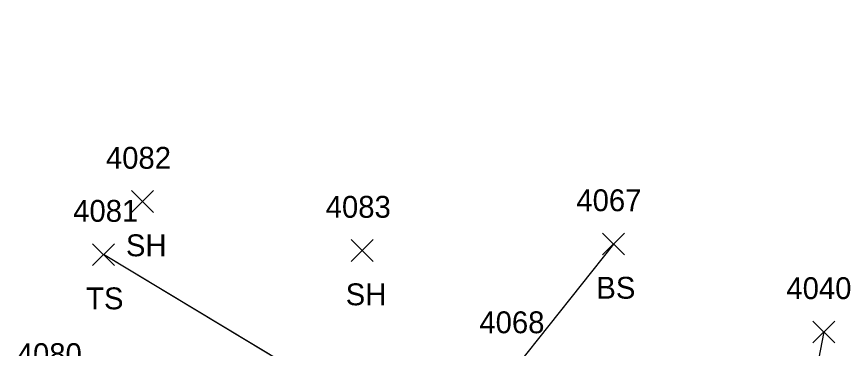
# Model space of a CAD drawing. Extents: x 1554668 to 1563881, y 831386 to 834374.
# Drawn here: x 1562190.3 to 1562266.5, y 834170.7 to 834201.1 of the extents above; entities that cross this region are included whole.
import ezdxf

# ---------------------------------------------------------------- set-up
doc = ezdxf.new("R2010")
doc.units = 0
for name, color, linetype in [('L_A', 7, 'Continuous'), ('L_I', 7, 'Continuous'), ('L_TIC', 7, 'Continuous'), ('LAWA', 7, 'Continuous'), ('LELB', 7, 'Continuous')]:
    doc.layers.add(name, color=color, linetype=linetype)

msp = doc.modelspace()

# ---------------------------------------------------------------- linework, layer by layer
at = {"layer": 'L_TIC'}
for points in [[(1562200.77, 834183.16), (1562202.77, 834185.16)], [(1562202.77, 834183.16), (1562200.77, 834185.16)], [(1562243.825, 834179.279), (1562245.825, 834181.279)], [(1562245.825, 834179.279), (1562243.825, 834181.279)], [(1562197.209, 834178.31), (1562199.209, 834180.31)], [(1562199.209, 834178.31), (1562197.209, 834180.31)], [(1562220.862, 834178.68), (1562222.862, 834180.68)], [(1562222.862, 834178.68), (1562220.862, 834180.68)], [(1562263.066, 834171.242), (1562265.066, 834173.242)], [(1562265.066, 834171.242), (1562263.066, 834173.242)]]:
    msp.add_lwpolyline(points, dxfattribs=at)
at = {"layer": 'LAWA'}
for points in [[(1562264.066, 834172.242), (1562260.28, 834152.616), (1562240.279, 834155.345), (1562220.249, 834159.389), (1562193.704, 834166.213), (1562151.516, 834189.235), (1562134.362, 834197.667), (1562108.95, 834212.49), (1562103.793, 834224.616), (1562105.925, 834242.465)], [(1562264.073, 834172.244), (1562260.287, 834152.618), (1562240.287, 834155.347), (1562220.256, 834159.393), (1562193.715, 834166.215), (1562151.519, 834189.239), (1562134.368, 834197.674), (1562108.954, 834212.498), (1562103.797, 834224.623), (1562105.929, 834242.473)], [(1562264.073, 834172.244), (1562260.287, 834152.618), (1562240.287, 834155.347), (1562220.256, 834159.393), (1562193.715, 834166.215), (1562151.519, 834189.239), (1562134.368, 834197.674), (1562108.954, 834212.498), (1562103.797, 834224.623), (1562105.929, 834242.473)], [(1562264.073, 834172.244), (1562260.287, 834152.618), (1562240.287, 834155.347), (1562220.256, 834159.393), (1562193.715, 834166.215), (1562151.519, 834189.239), (1562134.368, 834197.674), (1562108.954, 834212.498), (1562103.797, 834224.623), (1562105.929, 834242.473)]]:
    msp.add_lwpolyline(points, dxfattribs=at)
at = {"layer": 'LELB'}
for points in [[(1562244.825, 834180.279), (1562235.959, 834169.123), (1562225.766, 834162.716), (1562220.249, 834159.389)], [(1562244.833, 834180.281), (1562235.966, 834169.126), (1562225.775, 834162.717), (1562220.256, 834159.393)], [(1562244.833, 834180.281), (1562235.966, 834169.126), (1562225.775, 834162.717), (1562220.256, 834159.393)], [(1562244.833, 834180.281), (1562235.966, 834169.126), (1562225.775, 834162.717), (1562220.256, 834159.393)], [(1562238.678, 834156.759), (1562225.766, 834162.716), (1562198.209, 834179.31)], [(1562238.688, 834156.76), (1562225.775, 834162.717), (1562198.215, 834179.314)], [(1562238.688, 834156.76), (1562225.775, 834162.717), (1562198.215, 834179.314)], [(1562238.688, 834156.76), (1562225.775, 834162.717), (1562198.215, 834179.314)]]:
    msp.add_lwpolyline(points, dxfattribs=at)

# ---------------------------------------------------------------- texts
at = {"layer": 'L_A'}
for s, p in [('SH', (1562200.258, 834179.16)), ('BS', (1562243.266, 834175.279)), ('SH', (1562220.35, 834174.68)), ('TS', (1562196.618, 834174.31))]:
    msp.add_text(s, height=2, dxfattribs=at).set_placement(p)
at = {"layer": 'L_I'}
for s, p in [('4082', (1562198.431, 834187.16)), ('4067', (1562241.439, 834183.279)), ('4081', (1562195.437, 834182.31)), ('4083', (1562218.523, 834182.68)), ('4040', (1562260.641, 834175.242)), ('4068', (1562232.573, 834172.123)), ('4080', (1562190.279, 834169.213))]:
    msp.add_text(s, height=2, dxfattribs=at).set_placement(p)

doc.saveas('drawing.dxf')
